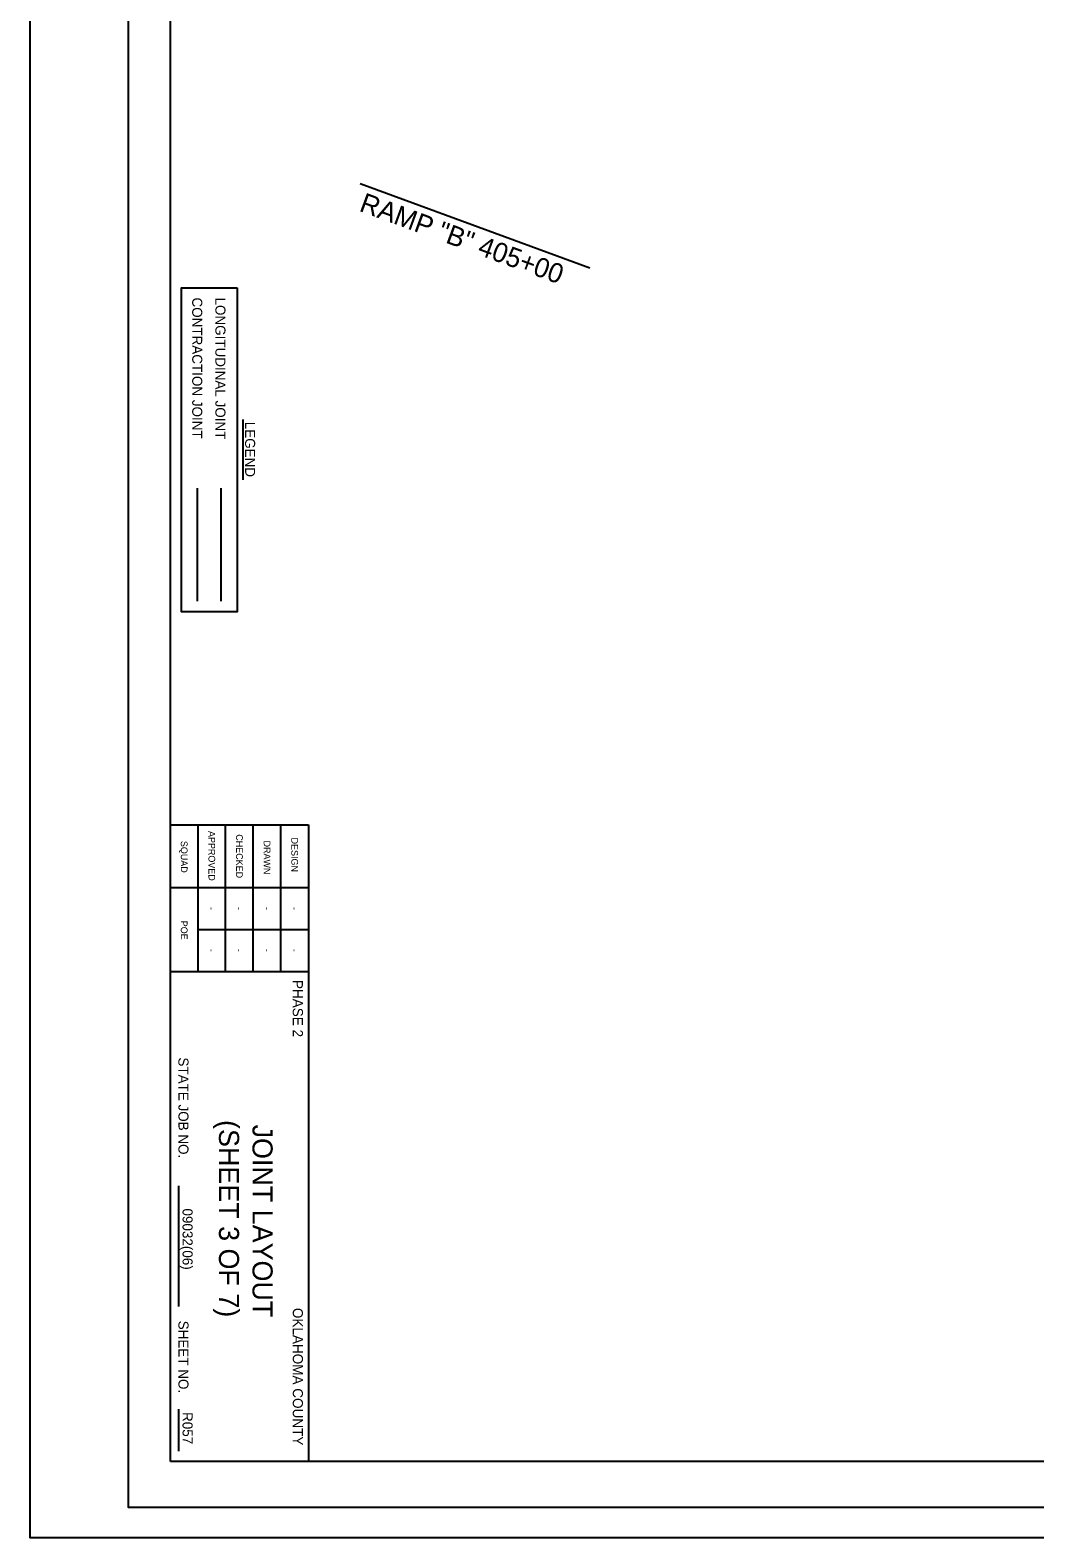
# Model space of a CAD drawing. Extents: x 2150474 to 2151194, y 143768 to 144848.
# Drawn here: x 2150474 to 2150834, y 143768 to 144308 of the extents above; entities that cross this region are included whole.
import ezdxf

# ---------------------------------------------------------------- set-up
doc = ezdxf.new("R2010")
doc.units = 0
for name, color, linetype in [('PR_Joint_Contraction', 7, 'Continuous'), ('PR_Joint_Long', 7, 'Continuous'), ('PR_Txt', 7, 'Continuous'), ('SHT_Match_Lines', 7, 'Continuous'), ('SHT_Plot_Shape_Full', 7, 'Continuous'), ('SHT_Plot_Shape_Half', 7, 'Continuous'), ('SHT_Sheet_Border', 7, 'Continuous'), ('SHT_Standard_Sheet_Lines', 7, 'Continuous'), ('SHT_Standard_Sheet_Txt', 7, 'Continuous')]:
    doc.layers.add(name, color=color, linetype=linetype)

msp = doc.modelspace()

# ---------------------------------------------------------------- linework, layer by layer
at = {"layer": 'PR_Joint_Contraction'}
msp.add_lwpolyline([(2150533.5, 144143.58), (2150533.5, 144103.16)], dxfattribs=at)
at = {"layer": 'PR_Joint_Long'}
msp.add_line((2150541.92, 144143.58), (2150541.92, 144103.16), dxfattribs=at)
at = {"layer": 'PR_Txt'}
msp.add_line((2150549.86, 144168.19), (2150549.86, 144146.58), dxfattribs=at)
msp.add_lwpolyline([(2150547.79, 144215.39), (2150547.79, 144099.38), (2150527.84, 144099.38), (2150527.84, 144215.39)], close=True, dxfattribs=at)
at = {"layer": 'SHT_Match_Lines'}
msp.add_line((2150674.18, 144222.47), (2150591.92, 144252.6), dxfattribs=at)
at = {"layer": 'SHT_Plot_Shape_Full'}
msp.add_lwpolyline([(2151193.63, 144847.67), (2151193.63, 143767.67), (2150473.63, 143767.67), (2150473.63, 144847.67)], close=True, dxfattribs=at)
at = {"layer": 'SHT_Plot_Shape_Half'}
msp.add_lwpolyline([(2151168.88, 144798.55), (2151168.88, 143778.55), (2150508.88, 143778.55), (2150508.88, 144798.55)], close=True, dxfattribs=at)
at = {"layer": 'SHT_Sheet_Border'}
for p, q in [((2150523.88, 144023.05), (2150573.38, 144023.05)), ((2150573.38, 144023.05), (2150573.39, 143795.05)), ((2150523.88, 143970.55), (2150573.41, 143970.55))]:
    msp.add_line(p, q, dxfattribs=at)
msp.add_lwpolyline([(2150523.88, 143795.05), (2150523.88, 144740.05), (2151153.88, 144740.05), (2151153.88, 143795.05)], close=True, dxfattribs=at)
at = {"layer": 'SHT_Standard_Sheet_Lines'}
for p, q in [((2150523.88, 144000.55), (2150573.41, 144000.55)), ((2150533.79, 143985.55), (2150573.41, 143985.55)), ((2150526.77, 143893.73), (2150526.77, 143850.52)), ((2150526.77, 143813.78), (2150526.77, 143798.71))]:
    msp.add_line(p, q, dxfattribs=at)
for points in [[(2150533.78, 143970.55), (2150533.78, 144023.05)], [(2150543.68, 143970.55), (2150543.68, 144023.05)], [(2150553.58, 143970.55), (2150553.58, 144023.05)], [(2150563.48, 143970.55), (2150563.48, 144023.05)]]:
    msp.add_lwpolyline(points, dxfattribs=at)

# ---------------------------------------------------------------- texts
at = {"layer": 'PR_Txt'}
for s, height, rotation, p in [('RAMP "B" 405+00', 7, 339.8495, (2150591.2, 144243.01)), ('CONTRACTION JOINT', 3.6, 270, (2150531.7, 144211.91)), ('LONGITUDINAL JOINT', 3.6, 270, (2150540.01, 144211.91)), ('LEGEND', 3.6, 270, (2150550.65, 144167.41))]:
    msp.add_text(s, height=height, rotation=rotation, dxfattribs=at).set_placement(p)
at = {"layer": 'SHT_Standard_Sheet_Txt'}
for s, height, p in [('APPROVED', 2.4, (2150537.53, 144020.84)), ('CHECKED', 2.4, (2150547.43, 144019.66)), ('DESIGN', 2.4, (2150567.23, 144018.48)), ('SQUAD', 2.4, (2150527.63, 144017.3)), ('DRAWN', 2.4, (2150557.33, 144017.41)), ('-', 2.4, (2150537.52, 143993.63)), ('-', 2.4, (2150547.42, 143993.63)), ('-', 2.4, (2150557.32, 143993.63)), ('-', 2.4, (2150567.25, 143993.63)), ('POE', 2.4, (2150527.63, 143988.7)), ('-', 2.4, (2150537.52, 143978.63)), ('-', 2.4, (2150547.42, 143978.63)), ('-', 2.4, (2150557.32, 143978.63)), ('-', 2.4, (2150567.25, 143978.63)), ('PHASE 2', 3.621, (2150567.75, 143967.48)), ('STATE JOB NO.', 3.6, (2150526.77, 143939.73)), ('(SHEET 3 OF 7)', 7.2, (2150541.29, 143917.3)), ('JOINT LAYOUT', 7.2, (2150553.31, 143915.68)), ('09032(06)', 3.6, (2150528.25, 143885.64)), ('SHEET NO. ', 3.6, (2150526.77, 143845.43)), ('OKLAHOMA COUNTY', 3.6211, (2150567.75, 143850.03)), ('R057', 3.6, (2150528.25, 143812.72))]:
    msp.add_text(s, height=height, rotation=270, dxfattribs=at).set_placement(p)

doc.saveas('drawing.dxf')
